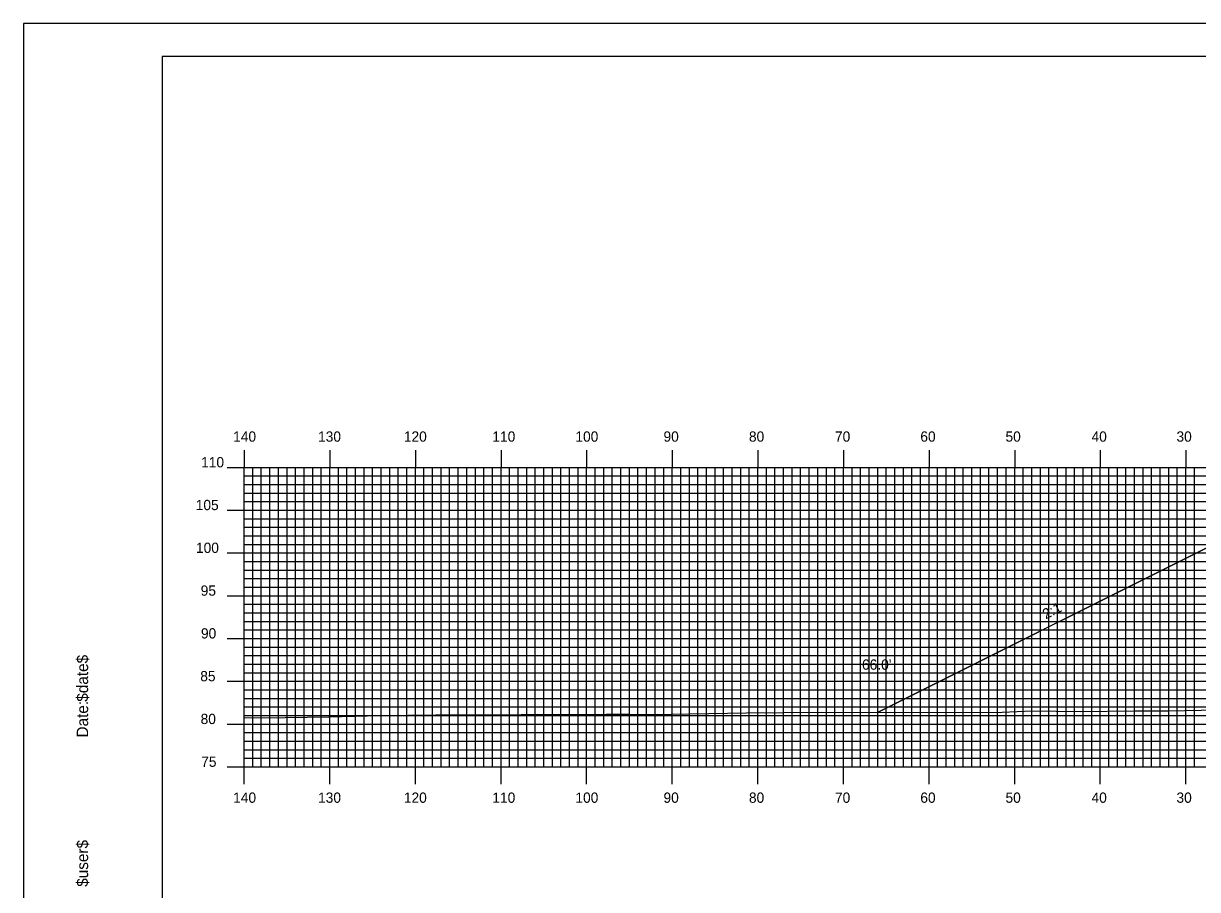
# Model space of a CAD drawing. Extents: x 1759430 to 1759773, y 442591 to 442811.
# Drawn here: x 1759429.9 to 1759567, y 442709.3 to 442810.5 of the extents above; entities that cross this region are included whole.
import ezdxf

# ---------------------------------------------------------------- set-up
doc = ezdxf.new("R2010")
doc.units = 0
for name, color, linetype in [('ANNOTATION', 7, 'Continuous'), ('BORDER', 7, 'Continuous'), ('D_Roadway_Centerline', 7, 'Continuous'), ('D_Roadway_SlopeLines', 7, 'Continuous'), ('D_Text_Standard', 7, 'Continuous'), ('H_V ANNOTATION', 7, 'Continuous'), ('MAJOR', 7, 'Continuous'), ('MINOR', 7, 'Continuous'), ('PLOT BOUNDARY', 7, 'Continuous'), ('S_Roadway_Centerline', 7, 'Continuous')]:
    doc.layers.add(name, color=color, linetype=linetype)

msp = doc.modelspace()

# ---------------------------------------------------------------- linework, layer by layer
at = {"layer": 'BORDER'}
msp.add_lwpolyline([(1759446.07, 442596.67), (1759766.07, 442596.67), (1759766.07, 442806.67), (1759446.07, 442806.67)], close=True, dxfattribs=at)
at = {"layer": 'D_Roadway_Centerline'}
msp.add_lwpolyline([(1759529.64, 442730.03), (1759567.38, 442748.9), (1759572.67, 442751.54), (1759575.67, 442751.66), (1759583.67, 442751.98), (1759595.67, 442752.41), (1759607.67, 442752.85), (1759619.67, 442753.28), (1759627.67, 442752.96), (1759630.67, 442752.84), (1759635.42, 442750.46), (1759672.99, 442731.68)], dxfattribs=at)
at = {"layer": 'D_Roadway_SlopeLines'}
msp.add_lwpolyline([(1759572.67, 442751.54), (1759529.64, 442730.03)], dxfattribs=at)
at = {"layer": 'MAJOR'}
for p, q in [((1759455.67, 442760.67), (1759455.67, 442758.67)), ((1759465.67, 442760.67), (1759465.67, 442758.67)), ((1759475.67, 442760.67), (1759475.67, 442758.67)), ((1759485.67, 442760.67), (1759485.67, 442758.67)), ((1759495.67, 442760.67), (1759495.67, 442758.67)), ((1759505.67, 442760.67), (1759505.67, 442758.67)), ((1759515.67, 442760.67), (1759515.67, 442758.67)), ((1759525.67, 442760.67), (1759525.67, 442758.67)), ((1759535.67, 442760.67), (1759535.67, 442758.67)), ((1759545.67, 442760.67), (1759545.67, 442758.67)), ((1759555.67, 442760.67), (1759555.67, 442758.67)), ((1759565.67, 442760.67), (1759565.67, 442758.67)), ((1759453.67, 442758.67), (1759455.67, 442758.67)), ((1759455.67, 442758.67), (1759735.67, 442758.67)), ((1759455.67, 442723.67), (1759455.67, 442758.67)), ((1759455.67, 442723.67), (1759455.67, 442758.67)), ((1759455.67, 442758.67), (1759735.67, 442758.67)), ((1759465.67, 442723.67), (1759465.67, 442758.67)), ((1759475.67, 442723.67), (1759475.67, 442758.67)), ((1759485.67, 442723.67), (1759485.67, 442758.67)), ((1759495.67, 442723.67), (1759495.67, 442758.67)), ((1759505.67, 442723.67), (1759505.67, 442758.67)), ((1759515.67, 442723.67), (1759515.67, 442758.67)), ((1759525.67, 442723.67), (1759525.67, 442758.67)), ((1759535.67, 442723.67), (1759535.67, 442758.67)), ((1759545.67, 442723.67), (1759545.67, 442758.67)), ((1759555.67, 442723.67), (1759555.67, 442758.67)), ((1759565.67, 442723.67), (1759565.67, 442758.67)), ((1759453.67, 442753.67), (1759455.67, 442753.67)), ((1759455.67, 442753.67), (1759735.67, 442753.67)), ((1759453.67, 442748.67), (1759455.67, 442748.67)), ((1759455.67, 442748.67), (1759735.67, 442748.67)), ((1759453.67, 442743.67), (1759455.67, 442743.67)), ((1759455.67, 442743.67), (1759735.67, 442743.67)), ((1759453.67, 442738.67), (1759455.67, 442738.67)), ((1759455.67, 442738.67), (1759735.67, 442738.67)), ((1759453.67, 442733.67), (1759455.67, 442733.67)), ((1759455.67, 442733.67), (1759735.67, 442733.67)), ((1759453.67, 442728.67), (1759455.67, 442728.67)), ((1759455.67, 442728.67), (1759735.67, 442728.67)), ((1759453.67, 442723.67), (1759455.67, 442723.67)), ((1759455.67, 442723.67), (1759735.67, 442723.67)), ((1759455.67, 442723.67), (1759735.67, 442723.67)), ((1759455.67, 442721.66), (1759455.67, 442723.67)), ((1759465.67, 442721.66), (1759465.67, 442723.67)), ((1759475.67, 442721.66), (1759475.67, 442723.67)), ((1759485.67, 442721.66), (1759485.67, 442723.67)), ((1759495.67, 442721.66), (1759495.67, 442723.67)), ((1759505.67, 442721.66), (1759505.67, 442723.67)), ((1759515.67, 442721.66), (1759515.67, 442723.67)), ((1759525.67, 442721.66), (1759525.67, 442723.67)), ((1759535.67, 442721.66), (1759535.67, 442723.67)), ((1759545.67, 442721.66), (1759545.67, 442723.67)), ((1759555.67, 442721.66), (1759555.67, 442723.67)), ((1759565.67, 442721.66), (1759565.67, 442723.67))]:
    msp.add_line(p, q, dxfattribs=at)
at = {"layer": 'MINOR'}
for p, q in [((1759456.67, 442723.67), (1759456.67, 442758.67)), ((1759457.67, 442723.67), (1759457.67, 442758.67)), ((1759458.67, 442723.67), (1759458.67, 442758.67)), ((1759459.67, 442723.67), (1759459.67, 442758.67)), ((1759460.67, 442723.67), (1759460.67, 442758.67)), ((1759461.67, 442723.67), (1759461.67, 442758.67)), ((1759462.67, 442723.67), (1759462.67, 442758.67)), ((1759463.67, 442723.67), (1759463.67, 442758.67)), ((1759464.67, 442723.67), (1759464.67, 442758.67)), ((1759466.67, 442723.67), (1759466.67, 442758.67)), ((1759467.67, 442723.67), (1759467.67, 442758.67)), ((1759468.67, 442723.67), (1759468.67, 442758.67)), ((1759469.67, 442723.67), (1759469.67, 442758.67)), ((1759470.67, 442723.67), (1759470.67, 442758.67)), ((1759471.67, 442723.67), (1759471.67, 442758.67)), ((1759472.67, 442723.67), (1759472.67, 442758.67)), ((1759473.67, 442723.67), (1759473.67, 442758.67)), ((1759474.67, 442723.67), (1759474.67, 442758.67)), ((1759476.67, 442723.67), (1759476.67, 442758.67)), ((1759477.67, 442723.67), (1759477.67, 442758.67)), ((1759478.67, 442723.67), (1759478.67, 442758.67)), ((1759479.67, 442723.67), (1759479.67, 442758.67)), ((1759480.67, 442723.67), (1759480.67, 442758.67)), ((1759481.67, 442723.67), (1759481.67, 442758.67)), ((1759482.67, 442723.67), (1759482.67, 442758.67)), ((1759483.67, 442723.67), (1759483.67, 442758.67)), ((1759484.67, 442723.67), (1759484.67, 442758.67)), ((1759486.67, 442723.67), (1759486.67, 442758.67)), ((1759487.67, 442723.67), (1759487.67, 442758.67)), ((1759488.67, 442723.67), (1759488.67, 442758.67)), ((1759489.67, 442723.67), (1759489.67, 442758.67)), ((1759490.67, 442723.67), (1759490.67, 442758.67)), ((1759491.67, 442723.67), (1759491.67, 442758.67)), ((1759492.67, 442723.67), (1759492.67, 442758.67)), ((1759493.67, 442723.67), (1759493.67, 442758.67)), ((1759494.67, 442723.67), (1759494.67, 442758.67)), ((1759496.67, 442723.67), (1759496.67, 442758.67)), ((1759497.67, 442723.67), (1759497.67, 442758.67)), ((1759498.67, 442723.67), (1759498.67, 442758.67)), ((1759499.67, 442723.67), (1759499.67, 442758.67)), ((1759500.67, 442723.67), (1759500.67, 442758.67)), ((1759501.67, 442723.67), (1759501.67, 442758.67)), ((1759502.67, 442723.67), (1759502.67, 442758.67)), ((1759503.67, 442723.67), (1759503.67, 442758.67)), ((1759504.67, 442723.67), (1759504.67, 442758.67)), ((1759506.67, 442723.67), (1759506.67, 442758.67)), ((1759507.67, 442723.67), (1759507.67, 442758.67)), ((1759508.67, 442723.67), (1759508.67, 442758.67)), ((1759509.67, 442723.67), (1759509.67, 442758.67)), ((1759510.67, 442723.67), (1759510.67, 442758.67)), ((1759511.67, 442723.67), (1759511.67, 442758.67)), ((1759512.67, 442723.67), (1759512.67, 442758.67)), ((1759513.67, 442723.67), (1759513.67, 442758.67)), ((1759514.67, 442723.67), (1759514.67, 442758.67)), ((1759516.67, 442723.67), (1759516.67, 442758.67)), ((1759517.67, 442723.67), (1759517.67, 442758.67)), ((1759518.67, 442723.67), (1759518.67, 442758.67)), ((1759519.67, 442723.67), (1759519.67, 442758.67)), ((1759520.67, 442723.67), (1759520.67, 442758.67)), ((1759521.67, 442723.67), (1759521.67, 442758.67)), ((1759522.67, 442723.67), (1759522.67, 442758.67)), ((1759523.67, 442723.67), (1759523.67, 442758.67)), ((1759524.67, 442723.67), (1759524.67, 442758.67)), ((1759526.67, 442723.67), (1759526.67, 442758.67)), ((1759527.67, 442723.67), (1759527.67, 442758.67)), ((1759528.67, 442723.67), (1759528.67, 442758.67)), ((1759529.67, 442723.67), (1759529.67, 442758.67)), ((1759530.67, 442723.67), (1759530.67, 442758.67)), ((1759531.67, 442723.67), (1759531.67, 442758.67)), ((1759532.67, 442723.67), (1759532.67, 442758.67)), ((1759533.67, 442723.67), (1759533.67, 442758.67)), ((1759534.67, 442723.67), (1759534.67, 442758.67)), ((1759536.67, 442723.67), (1759536.67, 442758.67)), ((1759537.67, 442723.67), (1759537.67, 442758.67)), ((1759538.67, 442723.67), (1759538.67, 442758.67)), ((1759539.67, 442723.67), (1759539.67, 442758.67)), ((1759540.67, 442723.67), (1759540.67, 442758.67)), ((1759541.67, 442723.67), (1759541.67, 442758.67)), ((1759542.67, 442723.67), (1759542.67, 442758.67)), ((1759543.67, 442723.67), (1759543.67, 442758.67)), ((1759544.67, 442723.67), (1759544.67, 442758.67)), ((1759546.67, 442723.67), (1759546.67, 442758.67)), ((1759547.67, 442723.67), (1759547.67, 442758.67)), ((1759548.67, 442723.67), (1759548.67, 442758.67)), ((1759549.67, 442723.67), (1759549.67, 442758.67)), ((1759550.67, 442723.67), (1759550.67, 442758.67)), ((1759551.67, 442723.67), (1759551.67, 442758.67)), ((1759552.67, 442723.67), (1759552.67, 442758.67)), ((1759553.67, 442723.67), (1759553.67, 442758.67)), ((1759554.67, 442723.67), (1759554.67, 442758.67)), ((1759556.67, 442723.67), (1759556.67, 442758.67)), ((1759557.67, 442723.67), (1759557.67, 442758.67)), ((1759558.67, 442723.67), (1759558.67, 442758.67)), ((1759559.67, 442723.67), (1759559.67, 442758.67)), ((1759560.67, 442723.67), (1759560.67, 442758.67)), ((1759561.67, 442723.67), (1759561.67, 442758.67)), ((1759562.67, 442723.67), (1759562.67, 442758.67)), ((1759563.67, 442723.67), (1759563.67, 442758.67)), ((1759564.67, 442723.67), (1759564.67, 442758.67)), ((1759566.67, 442723.67), (1759566.67, 442758.67)), ((1759455.67, 442757.67), (1759735.67, 442757.67)), ((1759455.67, 442757.67), (1759457.68, 442757.67)), ((1759455.67, 442756.67), (1759735.67, 442756.67)), ((1759455.67, 442756.67), (1759457.68, 442756.67)), ((1759455.67, 442755.67), (1759735.67, 442755.67)), ((1759455.67, 442755.67), (1759457.68, 442755.67)), ((1759455.67, 442754.67), (1759735.67, 442754.67)), ((1759455.67, 442754.67), (1759457.68, 442754.67)), ((1759455.67, 442752.67), (1759735.67, 442752.67)), ((1759455.67, 442752.67), (1759457.68, 442752.67)), ((1759455.67, 442751.67), (1759735.67, 442751.67)), ((1759455.67, 442751.67), (1759457.68, 442751.67)), ((1759455.67, 442750.67), (1759735.67, 442750.67)), ((1759455.67, 442750.67), (1759457.68, 442750.67)), ((1759455.67, 442749.67), (1759735.67, 442749.67)), ((1759455.67, 442749.67), (1759457.68, 442749.67)), ((1759455.67, 442747.67), (1759735.67, 442747.67)), ((1759455.67, 442747.67), (1759457.68, 442747.67)), ((1759455.67, 442746.67), (1759735.67, 442746.67)), ((1759455.67, 442746.67), (1759457.68, 442746.67)), ((1759455.67, 442745.67), (1759735.67, 442745.67)), ((1759455.67, 442745.67), (1759457.68, 442745.67)), ((1759455.67, 442744.67), (1759735.67, 442744.67)), ((1759455.67, 442744.67), (1759457.68, 442744.67)), ((1759455.67, 442742.67), (1759735.67, 442742.67)), ((1759455.67, 442742.67), (1759457.68, 442742.67)), ((1759455.67, 442741.67), (1759735.67, 442741.67)), ((1759455.67, 442741.67), (1759457.68, 442741.67)), ((1759455.67, 442740.67), (1759735.67, 442740.67)), ((1759455.67, 442740.67), (1759457.68, 442740.67)), ((1759455.67, 442739.67), (1759735.67, 442739.67)), ((1759455.67, 442739.67), (1759457.68, 442739.67)), ((1759455.67, 442737.67), (1759735.67, 442737.67)), ((1759455.67, 442737.67), (1759457.68, 442737.67)), ((1759455.67, 442736.67), (1759735.67, 442736.67)), ((1759455.67, 442736.67), (1759457.68, 442736.67)), ((1759455.67, 442735.67), (1759735.67, 442735.67)), ((1759455.67, 442735.67), (1759457.68, 442735.67)), ((1759455.67, 442734.67), (1759735.67, 442734.67)), ((1759455.67, 442734.67), (1759457.68, 442734.67)), ((1759455.67, 442732.67), (1759735.67, 442732.67)), ((1759455.67, 442732.67), (1759457.68, 442732.67)), ((1759455.67, 442731.67), (1759735.67, 442731.67)), ((1759455.67, 442731.67), (1759457.68, 442731.67)), ((1759455.67, 442730.67), (1759735.67, 442730.67)), ((1759455.67, 442730.67), (1759457.68, 442730.67)), ((1759455.67, 442729.67), (1759735.67, 442729.67)), ((1759455.67, 442729.67), (1759457.68, 442729.67)), ((1759455.67, 442727.67), (1759735.67, 442727.67)), ((1759455.67, 442727.67), (1759457.68, 442727.67)), ((1759455.67, 442726.67), (1759735.67, 442726.67)), ((1759455.67, 442726.67), (1759457.68, 442726.67)), ((1759455.67, 442725.67), (1759735.67, 442725.67)), ((1759455.67, 442725.67), (1759457.68, 442725.67)), ((1759455.67, 442724.67), (1759735.67, 442724.67)), ((1759455.67, 442724.67), (1759457.68, 442724.67))]:
    msp.add_line(p, q, dxfattribs=at)
at = {"layer": 'PLOT BOUNDARY'}
msp.add_lwpolyline([(1759429.89, 442590.55), (1759769.89, 442590.55), (1759769.89, 442810.55), (1759429.89, 442810.55)], close=True, dxfattribs=at)
at = {"layer": 'S_Roadway_Centerline'}
msp.add_lwpolyline([(1759455.67, 442729.4), (1759460.47, 442729.42), (1759465.54, 442729.5), (1759471.57, 442729.66), (1759478.04, 442729.74), (1759497.97, 442729.82), (1759500.61, 442729.82), (1759503.31, 442729.78), (1759514.34, 442729.97), (1759523.08, 442730.05), (1759526.32, 442730.02), (1759544.2, 442730.06), (1759547.71, 442730.21), (1759553.33, 442730.15), (1759559.68, 442730.21), (1759563.55, 442730.2), (1759581.08, 442730.58)], dxfattribs=at)

# ---------------------------------------------------------------- texts
at = {"layer": 'ANNOTATION'}
msp.add_text('2:1', height=1.2, rotation=26.5651, dxfattribs=at).set_placement((1759549.3, 442740.89))
at = {"layer": 'BORDER'}
for s, p in [('$date$', (1759437.44, 442731.28)), ('$date$', (1759437.44, 442731.28)), ('Date:', (1759437.44, 442727.1)), ('Date:', (1759437.44, 442727.1)), ('$user$', (1759437.44, 442709.65)), ('$user$', (1759437.44, 442709.65))]:
    msp.add_text(s, height=1.339, rotation=90, dxfattribs=at).set_placement(p)
at = {"layer": 'D_Text_Standard'}
msp.add_text("66.0'", height=1.2, dxfattribs=at).set_placement((1759527.84, 442735.02))
at = {"layer": 'H_V ANNOTATION'}
for s, p in [('140', (1759454.38, 442761.67)), ('130', (1759464.3, 442761.67)), ('120', (1759474.32, 442761.67)), ('110', (1759484.66, 442761.67)), ('100', (1759494.36, 442761.67)), ('90', (1759504.65, 442761.67)), ('80', (1759514.63, 442761.67)), ('70', (1759524.68, 442761.67)), ('60', (1759534.65, 442761.67)), ('50', (1759544.6, 442761.67)), ('40', (1759554.65, 442761.67)), ('30', (1759564.57, 442761.67)), ('110', (1759450.64, 442758.67)), ('105', (1759450.01, 442753.67)), ('100', (1759450.04, 442748.67)), ('95', (1759450.59, 442743.67)), ('90', (1759450.62, 442738.67)), ('85', (1759450.54, 442733.67)), ('80', (1759450.58, 442728.67)), ('75', (1759450.65, 442723.67)), ('140', (1759454.38, 442719.47)), ('130', (1759464.3, 442719.47)), ('120', (1759474.32, 442719.47)), ('110', (1759484.66, 442719.47)), ('100', (1759494.36, 442719.47)), ('90', (1759504.65, 442719.47)), ('80', (1759514.63, 442719.47)), ('70', (1759524.68, 442719.47)), ('60', (1759534.65, 442719.47)), ('50', (1759544.6, 442719.47)), ('40', (1759554.65, 442719.47)), ('30', (1759564.57, 442719.47))]:
    msp.add_text(s, height=1.2, dxfattribs=at).set_placement(p)
at = {"layer": 'MAJOR'}
msp.add_text('-', height=0.012, dxfattribs=at).set_placement((1759455.67, 442723.67))

doc.saveas('drawing.dxf')
